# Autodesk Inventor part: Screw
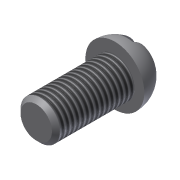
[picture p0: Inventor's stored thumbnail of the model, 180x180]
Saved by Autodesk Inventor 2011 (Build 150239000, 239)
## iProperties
Shininess: 77.0
Length Units: 11269
Angle Units: 11279
Time Units: 11290
Mass Units: 11283
Length Display Precision: 3
Angle Display Precision: 2
Created: 2002-01
Part Number: Screw
Document SubType Name: Modeling
Designer: ***
Density: 1 g/cm^3
Density: 0.0
Volumn: 0.0
Area: 0.0
PropertySet Name: Model Information
Control State: 0
Master: False
Checked Out: False
Author: ***
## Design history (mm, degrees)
sketch "Sketch1"
  geometry: L1 (-0.061, 13.328)-(-0.061, -1.672); L2 (-0.061, -1.672)-(14.939, -1.672); A1 r 15 centre (-0.061, -1.672) between (14.939, -1.672) and (-0.061, 13.328)
  constraints: 4 end point, 2 point on circle, 1 centre point
  dimensions: "d0" = 15 radius of A1
revolve "Revolution1" sketch "Sketch1" stored, may be unused: angle "d3" = 90 deg
workplane "Work Plane2"
sketch "Sketch3"
  geometry: L1 (-3, 26)-(3, 26); L2 (3, 26)-(3, 6); L3 (3, 6)-(-3, 6); L4 (-3, 6)-(-3, 26); L5 (-15, 0)-(15, 0) reference
  constraints: 8 end point, 2 parallel, 1 horizontal, 1 perpendicular
  dimensions: "d11" = 6 distance of L1.start L1.end; "d12" = 20 distance of L3.end L1.start; "d13" = 6 distance between parallel lines of L5 L3; "d14" = 12 distance from line of L4 L5.start
extrude "Extrusion2" cut sketch "Sketch3" stored distance "d15" = 10; taper "d16" = 0 deg
sketch "Sketch4"
  geometry: C1 r 10 at (0, -0.624)
  constraints: 1 centre point
  dimensions: "d17" = 20 diameter of C1
extrude "Extrusion3" join sketch "Sketch4" distance "d18" = 40; taper "d19" = 0 deg
chamfer "Chamfer1" distance "d20" = 2; stored, may be unused: second distance "d21" = 2, angle "d24" = 45 deg
thread "Thread1" dims "d22" = 10, "d23" = 0
body "Solid1"
